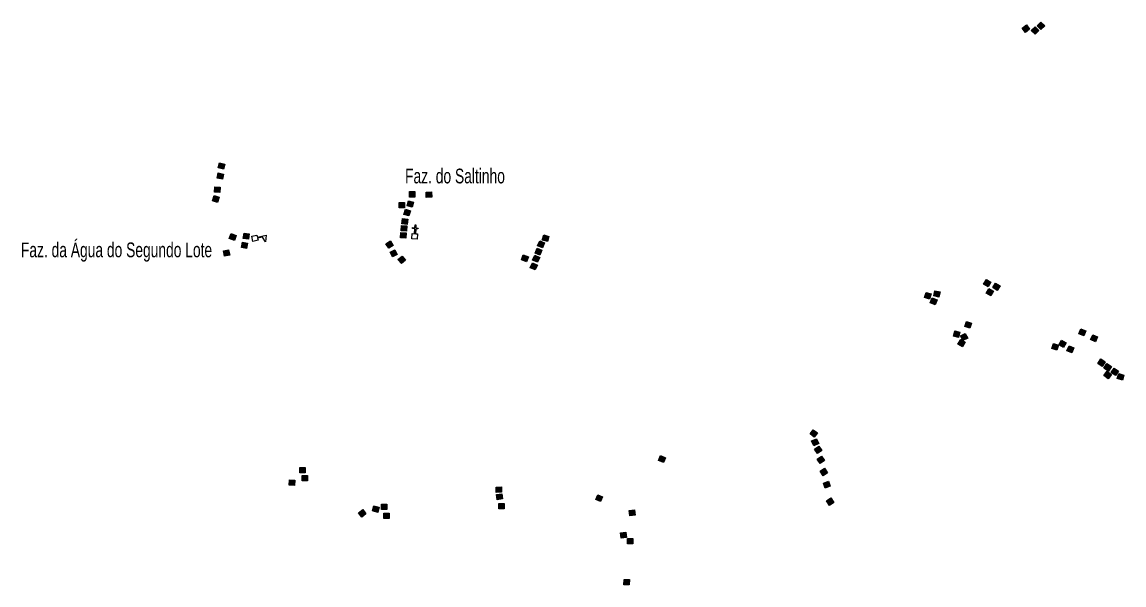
# Model space of a CAD drawing. Extents: x 679 to 705, y 7427.4 to 7455.4.
# Drawn here: x 692.77 to 698.74, y 7436.89 to 7439.95 of the extents above; entities that cross this region are included whole.
import ezdxf

# ---------------------------------------------------------------- set-up
doc = ezdxf.new("R2010")
doc.units = 0
doc.header["$LTSCALE"] = 0.032
for name, color, linetype, lineweight in [('2', 7, 'Continuous', 25), ('4', 7, 'Continuous', 25), ('6', 7, 'Continuous', 25)]:
    doc.layers.add(name, color=color, linetype=linetype, lineweight=lineweight)
doc.layers.add('61', color=7, linetype='Continuous')

msp = doc.modelspace()

# ---------------------------------------------------------------- hatches: boundary and pattern name
at = {"layer": '2'}
for points in [[(698.2104, 7439.929), (698.2281, 7439.9061), (698.2051, 7439.8884), (698.1874, 7439.9114)], [(698.2573, 7439.9196), (698.2778, 7439.8991), (698.2573, 7439.8786), (698.2368, 7439.8991)], [(698.289, 7439.9451), (698.3097, 7439.9249), (698.2895, 7439.9041), (698.2687, 7439.9244)], [(693.8649, 7439.1742), (693.8575, 7439.1462), (693.8295, 7439.1536), (693.8369, 7439.1817)], [(693.8581, 7439.1207), (693.8519, 7439.0924), (693.8236, 7439.0985), (693.8298, 7439.1269)], [(693.8408, 7439.0492), (693.838, 7439.0203), (693.8092, 7439.0231), (693.8119, 7439.0519)], [(693.8352, 7438.9946), (693.8262, 7438.967), (693.7986, 7438.976), (693.8076, 7439.0036)], [(694.8951, 7439.025), (694.8951, 7438.996), (694.8661, 7438.996), (694.8661, 7439.025)], [(694.9854, 7439.0239), (694.9866, 7438.9949), (694.9576, 7438.9938), (694.9565, 7439.0228)], [(694.8397, 7438.9656), (694.8389, 7438.9366), (694.8099, 7438.9374), (694.8107, 7438.9664)], [(694.8885, 7438.9687), (694.8815, 7438.9405), (694.8534, 7438.9475), (694.8604, 7438.9757)], [(694.8575, 7438.8756), (694.8534, 7438.8468), (694.8246, 7438.8509), (694.8287, 7438.8797)], [(694.8718, 7438.921), (694.8635, 7438.8932), (694.8357, 7438.9016), (694.844, 7438.9293)], [(694.8517, 7438.84), (694.8499, 7438.8111), (694.8209, 7438.8129), (694.8227, 7438.8418)], [(693.9265, 7438.7878), (693.9168, 7438.7604), (693.8895, 7438.7701), (693.8991, 7438.7974)], [(693.998, 7438.7955), (693.9934, 7438.7669), (693.9648, 7438.7715), (693.9694, 7438.8001)], [(694.7632, 7438.7582), (694.7787, 7438.7337), (694.7542, 7438.7182), (694.7387, 7438.7427)], [(694.8481, 7438.8021), (694.8471, 7438.7731), (694.8181, 7438.7742), (694.8192, 7438.8032)], [(695.599, 7438.7469), (695.5878, 7438.7201), (695.561, 7438.7313), (695.5722, 7438.758)], [(695.622, 7438.7823), (695.6138, 7438.7545), (695.586, 7438.7626), (695.5941, 7438.7905)], [(693.8859, 7438.7094), (693.892, 7438.6811), (693.8637, 7438.6749), (693.8576, 7438.7033)], [(693.9889, 7438.7455), (693.9832, 7438.717), (693.9548, 7438.7227), (693.9604, 7438.7511)], [(694.7874, 7438.7099), (694.8004, 7438.6839), (694.7744, 7438.671), (694.7615, 7438.6969)], [(695.5845, 7438.7073), (695.5737, 7438.6803), (695.5468, 7438.6911), (695.5576, 7438.718)], [(694.8262, 7438.6756), (694.8446, 7438.6532), (694.8222, 7438.6348), (694.8038, 7438.6572)], [(695.4834, 7438.6817), (695.5106, 7438.6719), (695.5009, 7438.6446), (695.4736, 7438.6544)], [(695.5594, 7438.6264), (695.5471, 7438.6002), (695.5208, 7438.6126), (695.5332, 7438.6388)], [(695.5721, 7438.6681), (695.56, 7438.6417), (695.5337, 7438.6538), (695.5458, 7438.6802)], [(698.0184, 7438.5333), (698.0031, 7438.5087), (697.9785, 7438.524), (697.9938, 7438.5486)], [(698.0678, 7438.5143), (698.0526, 7438.4896), (698.0279, 7438.5048), (698.0431, 7438.5295)], [(697.6664, 7438.4785), (697.6943, 7438.4703), (697.6861, 7438.4425), (697.6583, 7438.4507)], [(697.715, 7438.4876), (697.7432, 7438.4808), (697.7365, 7438.4526), (697.7083, 7438.4594)], [(698.0325, 7438.4848), (698.0185, 7438.4595), (697.9931, 7438.4735), (698.0071, 7438.4989)], [(697.7004, 7438.4492), (697.727, 7438.4378), (697.7156, 7438.4111), (697.689, 7438.4226)], [(697.9132, 7438.3121), (697.9037, 7438.2847), (697.8763, 7438.2941), (697.8857, 7438.3215)], [(698.5329, 7438.2698), (698.5221, 7438.2429), (698.4952, 7438.2536), (698.5059, 7438.2805)], [(697.85, 7438.2628), (697.8434, 7438.2345), (697.8151, 7438.2412), (697.8218, 7438.2694)], [(697.8795, 7438.2078), (697.8646, 7438.183), (697.8397, 7438.1979), (697.8547, 7438.2227)], [(697.8794, 7438.2564), (697.8924, 7438.2305), (697.8664, 7438.2175), (697.8535, 7438.2435)], [(698.4264, 7438.2046), (698.4115, 7438.1798), (698.3866, 7438.1947), (698.4015, 7438.2196)], [(698.5969, 7438.2373), (698.5853, 7438.2107), (698.5587, 7438.2223), (698.5703, 7438.2489)], [(698.3848, 7438.193), (698.3762, 7438.1653), (698.3485, 7438.1739), (698.3572, 7438.2016)], [(698.4685, 7438.177), (698.4574, 7438.1502), (698.4306, 7438.1614), (698.4418, 7438.1881)], [(698.6377, 7438.1019), (698.6219, 7438.0775), (698.5976, 7438.0933), (698.6134, 7438.1176)], [(698.6714, 7438.034), (698.6545, 7438.0104), (698.6309, 7438.0273), (698.6477, 7438.0509)], [(698.6711, 7438.0767), (698.6558, 7438.0521), (698.6312, 7438.0673), (698.6464, 7438.092)], [(698.7095, 7438.052), (698.6933, 7438.028), (698.6693, 7438.0443), (698.6855, 7438.0683)], [(698.7395, 7438.0302), (698.7308, 7438.0025), (698.7031, 7438.0112), (698.7118, 7438.0389)], [(697.0555, 7437.7338), (697.0785, 7437.7161), (697.0608, 7437.6932), (697.0379, 7437.7108)], [(697.073, 7437.6849), (697.0847, 7437.6584), (697.0582, 7437.6467), (697.0465, 7437.6732)], [(697.0854, 7437.6444), (697.1019, 7437.6206), (697.0781, 7437.6041), (697.0616, 7437.6279)], [(696.2547, 7437.582), (696.2437, 7437.5552), (696.2168, 7437.5662), (696.2278, 7437.593)], [(697.0995, 7437.5902), (697.1164, 7437.5666), (697.0928, 7437.5498), (697.0759, 7437.5734)], [(694.3007, 7437.5291), (694.3007, 7437.5001), (694.2717, 7437.5001), (694.2717, 7437.5291)], [(697.1159, 7437.5247), (697.1322, 7437.5007), (697.1082, 7437.4844), (697.0919, 7437.5084)], [(694.2446, 7437.4603), (694.2433, 7437.4314), (694.2144, 7437.4326), (694.2156, 7437.4616)], [(694.3142, 7437.4862), (694.3142, 7437.4572), (694.2852, 7437.4572), (694.2852, 7437.4862)], [(697.1372, 7437.455), (697.1475, 7437.4279), (697.1204, 7437.4175), (697.1101, 7437.4446)], [(695.3646, 7437.4233), (695.3653, 7437.3943), (695.3363, 7437.3936), (695.3356, 7437.4226)], [(695.3671, 7437.3868), (695.3712, 7437.3581), (695.3425, 7437.354), (695.3384, 7437.3827)], [(695.9135, 7437.3704), (695.9026, 7437.3436), (695.8757, 7437.3545), (695.8867, 7437.3814)], [(694.7015, 7437.3136), (694.6941, 7437.2856), (694.6661, 7437.293), (694.6734, 7437.321)], [(694.7429, 7437.3306), (694.7438, 7437.3016), (694.7148, 7437.3007), (694.7139, 7437.3297)], [(695.3804, 7437.333), (695.3804, 7437.304), (695.3514, 7437.304), (695.3514, 7437.333)], [(697.1511, 7437.3635), (697.1675, 7437.3396), (697.1436, 7437.3232), (697.1271, 7437.3471)], [(694.6125, 7437.3004), (694.6303, 7437.2775), (694.6074, 7437.2597), (694.5896, 7437.2826)], [(694.7564, 7437.2805), (694.7555, 7437.2515), (694.7265, 7437.2525), (694.7275, 7437.2814)], [(696.0858, 7437.2995), (696.0896, 7437.2707), (696.0608, 7437.267), (696.0571, 7437.2957)], [(696.0397, 7437.1784), (696.043, 7437.1495), (696.0142, 7437.1463), (696.0109, 7437.1751)], [(696.0779, 7437.1432), (696.0779, 7437.1142), (696.0489, 7437.1142), (696.0489, 7437.1432)], [(696.0587, 7436.9206), (696.0577, 7436.8916), (696.0288, 7436.8925), (696.0297, 7436.9215)]]:
    msp.add_hatch(color=256, dxfattribs=at).paths.add_polyline_path(points)

# ---------------------------------------------------------------- linework, layer by layer
for points in [[(698.2104, 7439.929), (698.2281, 7439.9061), (698.2051, 7439.8884), (698.1874, 7439.9114)], [(698.2573, 7439.9196), (698.2778, 7439.8991), (698.2573, 7439.8786), (698.2368, 7439.8991)], [(698.289, 7439.9451), (698.3097, 7439.9249), (698.2895, 7439.9041), (698.2687, 7439.9244)], [(693.8649, 7439.1742), (693.8575, 7439.1462), (693.8295, 7439.1536), (693.8369, 7439.1817)], [(693.8581, 7439.1207), (693.8519, 7439.0924), (693.8236, 7439.0985), (693.8298, 7439.1269)], [(693.8408, 7439.0492), (693.838, 7439.0203), (693.8092, 7439.0231), (693.8119, 7439.0519)], [(693.8352, 7438.9946), (693.8262, 7438.967), (693.7986, 7438.976), (693.8076, 7439.0036)], [(694.8951, 7439.025), (694.8951, 7438.996), (694.8661, 7438.996), (694.8661, 7439.025)], [(694.9854, 7439.0239), (694.9866, 7438.9949), (694.9576, 7438.9938), (694.9565, 7439.0228)], [(694.8397, 7438.9656), (694.8389, 7438.9366), (694.8099, 7438.9374), (694.8107, 7438.9664)], [(694.8885, 7438.9687), (694.8815, 7438.9405), (694.8534, 7438.9475), (694.8604, 7438.9757)], [(694.8575, 7438.8756), (694.8534, 7438.8468), (694.8246, 7438.8509), (694.8287, 7438.8797)], [(694.8718, 7438.921), (694.8635, 7438.8932), (694.8357, 7438.9016), (694.844, 7438.9293)], [(694.8517, 7438.84), (694.8499, 7438.8111), (694.8209, 7438.8129), (694.8227, 7438.8418)], [(693.9265, 7438.7878), (693.9168, 7438.7604), (693.8895, 7438.7701), (693.8991, 7438.7974)], [(693.998, 7438.7955), (693.9934, 7438.7669), (693.9648, 7438.7715), (693.9694, 7438.8001)], [(694.7632, 7438.7582), (694.7787, 7438.7337), (694.7542, 7438.7182), (694.7387, 7438.7427)], [(694.8481, 7438.8021), (694.8471, 7438.7731), (694.8181, 7438.7742), (694.8192, 7438.8032)], [(695.599, 7438.7469), (695.5878, 7438.7201), (695.561, 7438.7313), (695.5722, 7438.758)], [(695.622, 7438.7823), (695.6138, 7438.7545), (695.586, 7438.7626), (695.5941, 7438.7905)], [(693.8859, 7438.7094), (693.892, 7438.6811), (693.8637, 7438.6749), (693.8576, 7438.7033)], [(693.9889, 7438.7455), (693.9832, 7438.717), (693.9548, 7438.7227), (693.9604, 7438.7511)], [(694.7874, 7438.7099), (694.8004, 7438.6839), (694.7744, 7438.671), (694.7615, 7438.6969)], [(695.5845, 7438.7073), (695.5737, 7438.6803), (695.5468, 7438.6911), (695.5576, 7438.718)], [(694.8262, 7438.6756), (694.8446, 7438.6532), (694.8222, 7438.6348), (694.8038, 7438.6572)], [(695.4834, 7438.6817), (695.5106, 7438.6719), (695.5009, 7438.6446), (695.4736, 7438.6544)], [(695.5594, 7438.6264), (695.5471, 7438.6002), (695.5208, 7438.6126), (695.5332, 7438.6388)], [(695.5721, 7438.6681), (695.56, 7438.6417), (695.5337, 7438.6538), (695.5458, 7438.6802)], [(698.0184, 7438.5333), (698.0031, 7438.5087), (697.9785, 7438.524), (697.9938, 7438.5486)], [(698.0678, 7438.5143), (698.0526, 7438.4896), (698.0279, 7438.5048), (698.0431, 7438.5295)], [(697.6664, 7438.4785), (697.6943, 7438.4703), (697.6861, 7438.4425), (697.6583, 7438.4507)], [(697.715, 7438.4876), (697.7432, 7438.4808), (697.7365, 7438.4526), (697.7083, 7438.4594)], [(698.0325, 7438.4848), (698.0185, 7438.4595), (697.9931, 7438.4735), (698.0071, 7438.4989)], [(697.7004, 7438.4492), (697.727, 7438.4378), (697.7156, 7438.4111), (697.689, 7438.4226)], [(697.9132, 7438.3121), (697.9037, 7438.2847), (697.8763, 7438.2941), (697.8857, 7438.3215)], [(698.5329, 7438.2698), (698.5221, 7438.2429), (698.4952, 7438.2536), (698.5059, 7438.2805)], [(697.85, 7438.2628), (697.8434, 7438.2345), (697.8151, 7438.2412), (697.8218, 7438.2694)], [(697.8795, 7438.2078), (697.8646, 7438.183), (697.8397, 7438.1979), (697.8547, 7438.2227)], [(697.8794, 7438.2564), (697.8924, 7438.2305), (697.8664, 7438.2175), (697.8535, 7438.2435)], [(698.4264, 7438.2046), (698.4115, 7438.1798), (698.3866, 7438.1947), (698.4015, 7438.2196)], [(698.5969, 7438.2373), (698.5853, 7438.2107), (698.5587, 7438.2223), (698.5703, 7438.2489)], [(698.3848, 7438.193), (698.3762, 7438.1653), (698.3485, 7438.1739), (698.3572, 7438.2016)], [(698.4685, 7438.177), (698.4574, 7438.1502), (698.4306, 7438.1614), (698.4418, 7438.1881)], [(698.6377, 7438.1019), (698.6219, 7438.0775), (698.5976, 7438.0933), (698.6134, 7438.1176)], [(698.6714, 7438.034), (698.6545, 7438.0104), (698.6309, 7438.0273), (698.6477, 7438.0509)], [(698.6711, 7438.0767), (698.6558, 7438.0521), (698.6312, 7438.0673), (698.6464, 7438.092)], [(698.7095, 7438.052), (698.6933, 7438.028), (698.6693, 7438.0443), (698.6855, 7438.0683)], [(698.7395, 7438.0302), (698.7308, 7438.0025), (698.7031, 7438.0112), (698.7118, 7438.0389)], [(697.0555, 7437.7338), (697.0785, 7437.7161), (697.0608, 7437.6932), (697.0379, 7437.7108)], [(697.073, 7437.6849), (697.0847, 7437.6584), (697.0582, 7437.6467), (697.0465, 7437.6732)], [(697.0854, 7437.6444), (697.1019, 7437.6206), (697.0781, 7437.6041), (697.0616, 7437.6279)], [(696.2547, 7437.582), (696.2437, 7437.5552), (696.2168, 7437.5662), (696.2278, 7437.593)], [(697.0995, 7437.5902), (697.1164, 7437.5666), (697.0928, 7437.5498), (697.0759, 7437.5734)], [(694.3007, 7437.5291), (694.3007, 7437.5001), (694.2717, 7437.5001), (694.2717, 7437.5291)], [(697.1159, 7437.5247), (697.1322, 7437.5007), (697.1082, 7437.4844), (697.0919, 7437.5084)], [(694.2446, 7437.4603), (694.2433, 7437.4314), (694.2144, 7437.4326), (694.2156, 7437.4616)], [(694.3142, 7437.4862), (694.3142, 7437.4572), (694.2852, 7437.4572), (694.2852, 7437.4862)], [(697.1372, 7437.455), (697.1475, 7437.4279), (697.1204, 7437.4175), (697.1101, 7437.4446)], [(695.3646, 7437.4233), (695.3653, 7437.3943), (695.3363, 7437.3936), (695.3356, 7437.4226)], [(695.3671, 7437.3868), (695.3712, 7437.3581), (695.3425, 7437.354), (695.3384, 7437.3827)], [(695.9135, 7437.3704), (695.9026, 7437.3436), (695.8757, 7437.3545), (695.8867, 7437.3814)], [(694.7015, 7437.3136), (694.6941, 7437.2856), (694.6661, 7437.293), (694.6734, 7437.321)], [(694.7429, 7437.3306), (694.7438, 7437.3016), (694.7148, 7437.3007), (694.7139, 7437.3297)], [(695.3804, 7437.333), (695.3804, 7437.304), (695.3514, 7437.304), (695.3514, 7437.333)], [(697.1511, 7437.3635), (697.1675, 7437.3396), (697.1436, 7437.3232), (697.1271, 7437.3471)], [(694.6125, 7437.3004), (694.6303, 7437.2775), (694.6074, 7437.2597), (694.5896, 7437.2826)], [(694.7564, 7437.2805), (694.7555, 7437.2515), (694.7265, 7437.2525), (694.7275, 7437.2814)], [(696.0858, 7437.2995), (696.0896, 7437.2707), (696.0608, 7437.267), (696.0571, 7437.2957)], [(696.0397, 7437.1784), (696.043, 7437.1495), (696.0142, 7437.1463), (696.0109, 7437.1751)], [(696.0779, 7437.1432), (696.0779, 7437.1142), (696.0489, 7437.1142), (696.0489, 7437.1432)], [(696.0587, 7436.9206), (696.0577, 7436.8916), (696.0288, 7436.8925), (696.0297, 7436.9215)]]:
    msp.add_lwpolyline(points, close=True, dxfattribs=at)
at = {"layer": '4'}
for points in [[(694.0432, 7438.773), (694.0459, 7438.7612), (694.0176, 7438.7549), (694.0112, 7438.7832), (694.0395, 7438.7895), (694.0421, 7438.7778)], [(694.0421, 7438.7778), (694.0894, 7438.7884), (694.0855, 7438.7528), (694.0687, 7438.7788), (694.0432, 7438.773)]]:
    msp.add_lwpolyline(points, dxfattribs=at)
at = {"layer": '6'}
for points in [[(694.8934, 7438.797), (694.8953, 7438.824), (694.8832, 7438.8248), (694.8835, 7438.8297), (694.8956, 7438.8289), (694.8967, 7438.8452), (694.9015, 7438.8449), (694.9004, 7438.8286), (694.9125, 7438.8277), (694.9121, 7438.8228), (694.9001, 7438.8237), (694.8982, 7438.7966)], [(694.8982, 7438.7966), (694.9103, 7438.7958), (694.9083, 7438.7669), (694.8794, 7438.7688), (694.8814, 7438.7978), (694.8934, 7438.797)]]:
    msp.add_lwpolyline(points, dxfattribs=at)

# ---------------------------------------------------------------- texts
at = {"layer": '61', "width": 0.7}
for s, p in [('Faz. do Saltinho', (694.8424, 7439.07)), ('Faz. da Água do Segundo Lote', (692.7598, 7438.6692))]:
    msp.add_text(s, height=0.08, dxfattribs=at).set_placement(p)

doc.saveas('drawing.dxf')
